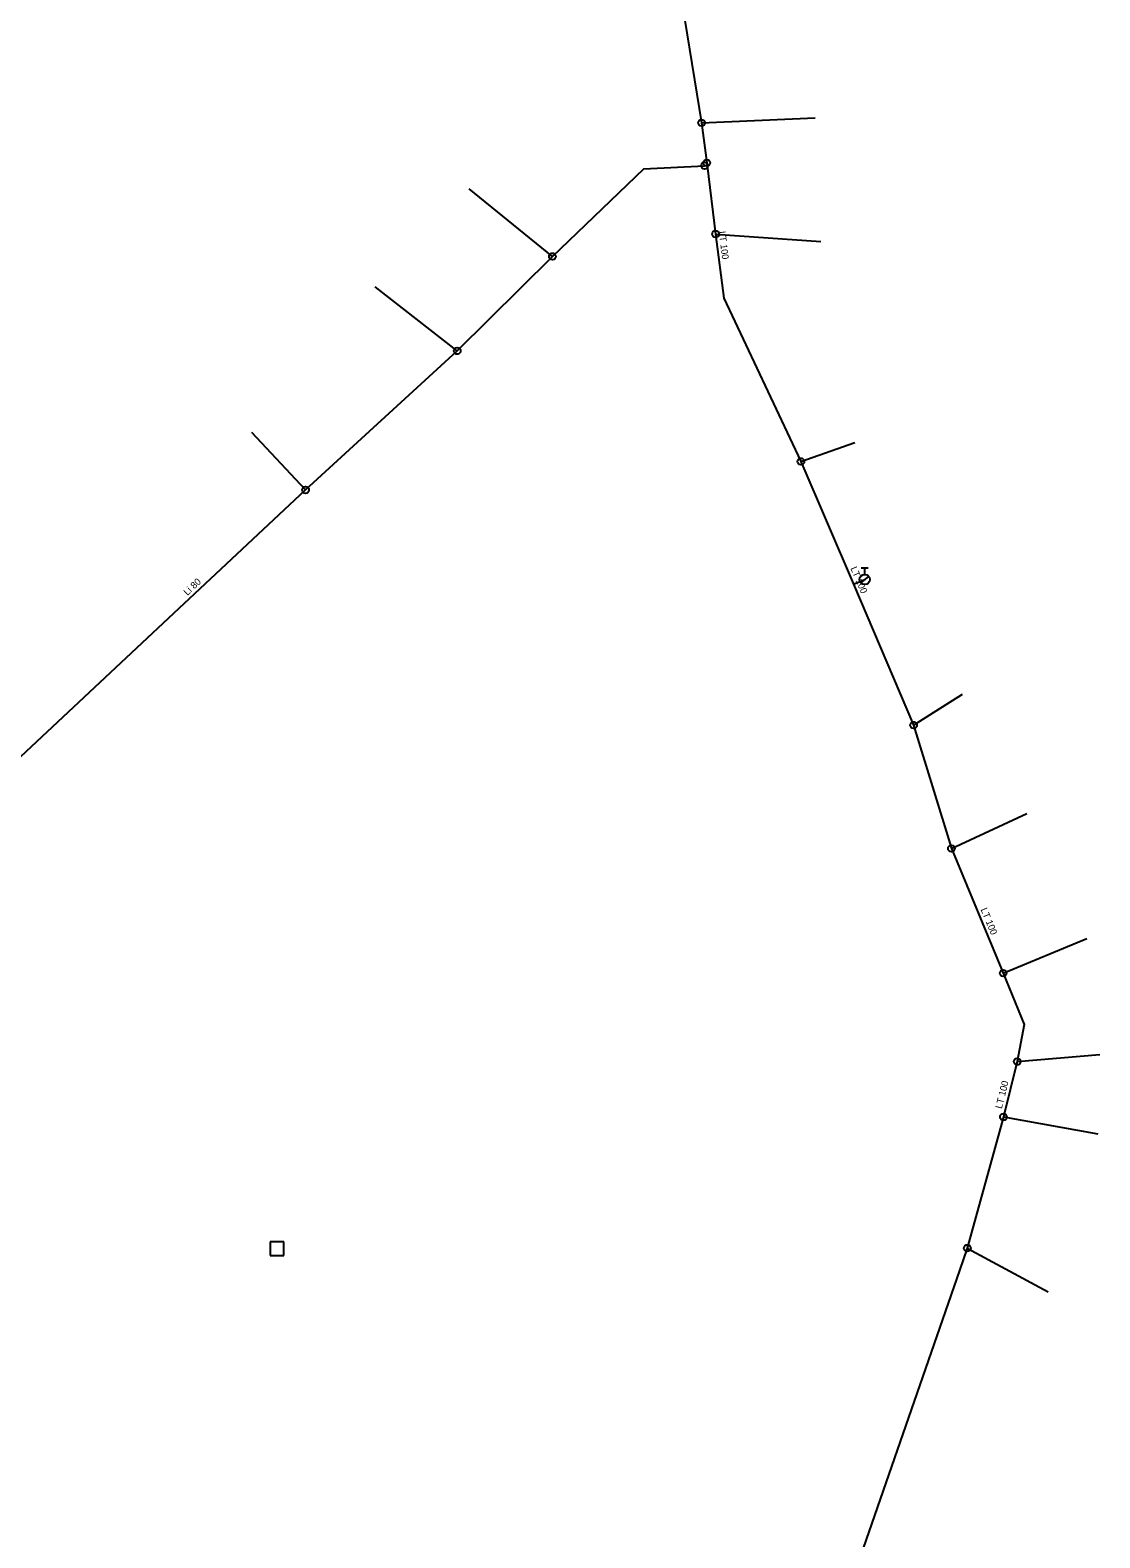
# Model space of a CAD drawing. Extents: x -684724 to -684366, y -1163865 to -1163489.
# Drawn here: x -684510 to -684431.3, y -1163713.4 to -1163602.4 of the extents above; entities that cross this region are included whole.
import ezdxf

# ---------------------------------------------------------------- set-up
doc = ezdxf.new("R2010")
doc.units = 0
for name, color, linetype in [('Hydranty', 7, 'Continuous'), ('Popis vodovodních řadů', 7, 'Continuous'), ('Vod přípojky-voda pitná', 7, 'Continuous'), ('Vodovodní řad', 7, 'Continuous'), ('Vodovodní šachty', 7, 'Continuous'), ('Vodovodní šoupata', 7, 'Continuous')]:
    doc.layers.add(name, color=color, linetype=linetype)

msp = doc.modelspace()

# ---------------------------------------------------------------- linework, layer by layer
at = {"layer": 'Hydranty'}
for p, q in [((-684448.86, -1163643.07), (-684448.27, -1163642.61)), ((-684448.82, -1163641.97), (-684448.32, -1163641.97)), ((-684448.57, -1163642.47), (-684448.57, -1163641.97))]:
    msp.add_line(p, q, dxfattribs=at)
msp.add_circle((-684448.57, -1163642.84), 0.375, dxfattribs=at)
at = {"layer": 'Vod přípojky-voda pitná'}
for points in [[(-684460.58, -1163609.2), (-684452.22, -1163608.83)], [(-684471.57, -1163619.04), (-684477.69, -1163614.07)], [(-684459.55, -1163617.39), (-684451.81, -1163617.95)], [(-684478.58, -1163626), (-684484.63, -1163621.29)], [(-684489.75, -1163636.24), (-684493.71, -1163632)], [(-684453.27, -1163634.14), (-684449.29, -1163632.75)], [(-684444.97, -1163653.56), (-684441.36, -1163651.29)], [(-684442.18, -1163662.65), (-684436.63, -1163660.07)], [(-684438.37, -1163671.83), (-684432.21, -1163669.27)], [(-684437.33, -1163678.34), (-684431.25, -1163677.83)], [(-684438.35, -1163682.42), (-684431.41, -1163683.66)], [(-684441.01, -1163692.08), (-684435.05, -1163695.29)]]:
    msp.add_lwpolyline(points, dxfattribs=at)
at = {"layer": 'Vodovodní řad'}
for points in [[(-684464.88, -1163521.35), (-684464.85, -1163522.74), (-684464.75, -1163527.3), (-684464.83, -1163538.46), (-684464.55, -1163543.94), (-684464.08, -1163552.95), (-684464.11, -1163559.94), (-684464.03, -1163571.18), (-684463.97, -1163575.6), (-684463.24, -1163583.66), (-684463.24, -1163587.15), (-684461.85, -1163598.43), (-684461.81, -1163601.67), (-684460.58, -1163609.2), (-684460.2, -1163612.15)], [(-684535.18, -1163678.76), (-684522.28, -1163666.69), (-684511.88, -1163656.95), (-684489.75, -1163636.24), (-684478.58, -1163626), (-684471.57, -1163619.04), (-684464.84, -1163612.59), (-684460.37, -1163612.36)], [(-684460.17, -1163612.35), (-684460.37, -1163612.36)], [(-684460.17, -1163612.35), (-684460.2, -1163612.15)], [(-684460.17, -1163612.35), (-684459.55, -1163617.39), (-684458.94, -1163622.12)], [(-684458.94, -1163622.12), (-684453.27, -1163634.14), (-684449.4, -1163643.17), (-684444.97, -1163653.56), (-684442.18, -1163662.65)], [(-684449.4, -1163643.17), (-684448.57, -1163642.84)], [(-684442.18, -1163662.65), (-684438.37, -1163671.83)], [(-684438.37, -1163671.83), (-684436.83, -1163675.61), (-684437.33, -1163678.34), (-684438.35, -1163682.42), (-684441.01, -1163692.08)], [(-684441.01, -1163692.08), (-684441.59, -1163693.72)], [(-684441.59, -1163693.72), (-684450.35, -1163719), (-684452.13, -1163723.25), (-684458.24, -1163736.95), (-684458.9, -1163738.57)]]:
    msp.add_lwpolyline(points, dxfattribs=at)
at = {"layer": 'Vodovodní šachty'}
for p, q in [((-684491.36, -1163691.63), (-684492.36, -1163691.63)), ((-684492.36, -1163691.63), (-684492.36, -1163692.63)), ((-684491.36, -1163692.63), (-684491.36, -1163691.63)), ((-684492.36, -1163692.63), (-684491.36, -1163692.63))]:
    msp.add_line(p, q, dxfattribs=at)
at = {"layer": 'Vodovodní šoupata'}
for centre in [(-684460.58, -1163609.2), (-684460.37, -1163612.36), (-684460.2, -1163612.15), (-684459.55, -1163617.39), (-684471.57, -1163619.04), (-684478.58, -1163626), (-684453.27, -1163634.14), (-684489.75, -1163636.24), (-684444.97, -1163653.56), (-684442.18, -1163662.65), (-684438.37, -1163671.83), (-684437.33, -1163678.34), (-684438.35, -1163682.42), (-684441.01, -1163692.08)]:
    msp.add_circle(centre, 0.25, dxfattribs=at)

# ---------------------------------------------------------------- texts
at = {"layer": 'Popis vodovodních řadů'}
for s, rotation, p in [('LT 100', 277.0131, (-684459.32, -1163617.21)), ('LT 100', 293.1986, (-684449.63, -1163642.01)), ('Li 80', 43.1015, (-684498.46, -1163644.05)), ('LT 100', 292.54, (-684440.04, -1163667.14)), ('LT 100', 75.9638, (-684438.47, -1163681.85))]:
    msp.add_text(s, height=0.5, rotation=rotation, dxfattribs=at).set_placement(p)

doc.saveas('drawing.dxf')
